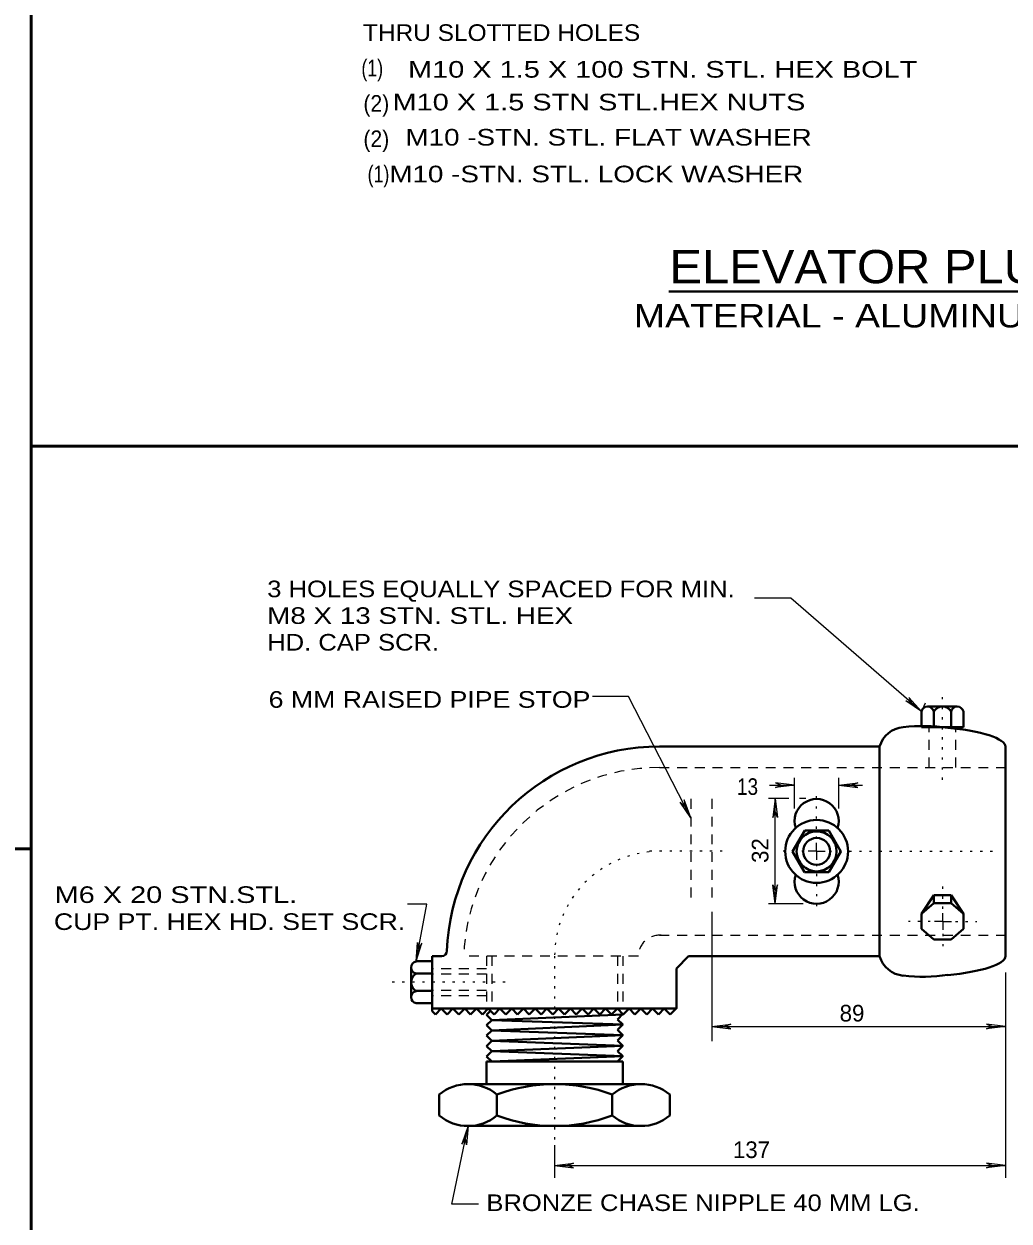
# Model space of a CAD drawing. Extents: x 312583 to 312854, y 144419 to 144597.
# Drawn here: x 312724.6 to 312769.6, y 144481.2 to 144536 of the extents above; entities that cross this region are included whole.
import ezdxf
from ezdxf.enums import TextEntityAlignment as Align

# ---------------------------------------------------------------- set-up
doc = ezdxf.new("R2010")
doc.units = 0
doc.header["$LTSCALE"] = 0.3
doc.linetypes.add('DOTTED', pattern=[1.5, 0.3, -1.2])
doc.linetypes.add('SHORT_DASHED', pattern=[2.7, 1.5, -1.2])
doc.layers.add('1', color=7, linetype='Continuous', lineweight=40)
doc.layers.add('2', color=7, linetype='Continuous', lineweight=13)

msp = doc.modelspace()

# ---------------------------------------------------------------- linework, layer by layer
at = {"layer": '1', "lineweight": 53}
for p, q in [((312805.4109, 144516.6626), (312724.8828, 144516.6626)), ((312724.8828, 144498.2549), (312684.879, 144498.2549))]:
    msp.add_line(p, q, dxfattribs=at)
at = {"layer": '1', "linetype": 'DOTTED', "lineweight": 13}
for p, q in [((312766.533, 144501.4167), (312766.533, 144505.5337)), ((312746.546, 144492.1553), (312741.3404, 144492.1553))]:
    msp.add_line(p, q, dxfattribs=at)
at = {"layer": '1'}
for p, q in [((312767.2, 144504.7593), (312765.843, 144504.7593)), ((312765.5747, 144504.5293), (312765.5747, 144503.8163)), ((312766.1344, 144504.5293), (312766.1344, 144503.8163)), ((312766.9317, 144504.5293), (312766.9317, 144503.8163)), ((312767.4914, 144504.5293), (312767.4914, 144503.8163)), ((312765.5747, 144503.8163), (312767.4914, 144503.8163)), ((312759.679, 144498.1353), (312760.2387, 144499.1013)), ((312760.231, 144497.1847), (312759.679, 144498.1353)), ((312766.1344, 144496.1343), (312765.5747, 144495.291)), ((312766.9317, 144496.1343), (312766.1344, 144496.1343)), ((312766.1344, 144496.1343), (312766.1344, 144495.774)), ((312766.9317, 144496.1343), (312766.9317, 144495.774)), ((312766.1344, 144495.774), (312765.5747, 144495.291)), ((312766.9317, 144495.774), (312766.1344, 144495.774)), ((312765.5747, 144495.291), (312765.5747, 144494.601)), ((312767.4914, 144495.291), (312767.4914, 144494.601)), ((312765.5747, 144494.601), (312766.1344, 144494.1103)), ((312767.4914, 144494.601), (312766.9317, 144494.1103)), ((312766.9317, 144494.1103), (312766.1344, 144494.1103)), ((312743.211, 144493.3513), (312743.648, 144493.3513)), ((312754.3737, 144492.7917), (312754.9334, 144493.3513)), ((312742.2527, 144492.8223), (312742.2527, 144491.4577)), ((312742.4827, 144493.1137), (312743.1957, 144493.1137)), ((312742.4827, 144492.554), (312743.1957, 144492.554)), ((312742.4827, 144491.7567), (312743.1957, 144491.7567)), ((312742.4827, 144491.197), (312743.1957, 144491.197)), ((312743.625, 144490.9517), (312743.3567, 144490.6833)), ((312743.625, 144490.9517), (312743.8934, 144490.6833)), ((312744.1617, 144490.9517), (312743.8934, 144490.6833)), ((312744.1617, 144490.9517), (312744.43, 144490.6833)), ((312744.6984, 144490.9517), (312744.43, 144490.6833)), ((312744.6984, 144490.9517), (312744.9667, 144490.6833)), ((312745.235, 144490.9517), (312744.9667, 144490.6833)), ((312745.235, 144490.9517), (312745.5034, 144490.6833)), ((312745.7717, 144490.9517), (312745.5034, 144490.6833)), ((312745.7717, 144490.9517), (312746.04, 144490.6833)), ((312746.3084, 144490.9517), (312746.04, 144490.6833)), ((312746.3084, 144490.9517), (312746.5767, 144490.6833)), ((312746.845, 144490.9517), (312746.5767, 144490.6833)), ((312746.845, 144490.9517), (312747.1134, 144490.6833)), ((312747.3817, 144490.9517), (312747.1134, 144490.6833)), ((312747.3817, 144490.9517), (312747.65, 144490.6833)), ((312747.9184, 144490.9517), (312747.65, 144490.6833)), ((312747.9184, 144490.9517), (312748.1867, 144490.6833)), ((312748.455, 144490.9517), (312748.1867, 144490.6833)), ((312748.455, 144490.9517), (312748.7234, 144490.6833)), ((312748.9917, 144490.9517), (312748.7234, 144490.6833)), ((312748.9917, 144490.9517), (312749.26, 144490.6833)), ((312749.5284, 144490.9517), (312749.26, 144490.6833)), ((312749.5284, 144490.9517), (312749.7967, 144490.6833)), ((312750.065, 144490.9517), (312749.7967, 144490.6833)), ((312750.065, 144490.9517), (312750.3334, 144490.6833)), ((312750.6017, 144490.9517), (312750.3334, 144490.6833)), ((312750.6017, 144490.9517), (312750.87, 144490.6833)), ((312751.1384, 144490.9517), (312750.87, 144490.6833)), ((312751.1384, 144490.9517), (312751.4067, 144490.6833)), ((312751.675, 144490.9517), (312751.4067, 144490.6833)), ((312751.675, 144490.9517), (312751.9434, 144490.6833)), ((312752.2117, 144490.9517), (312751.9434, 144490.6833)), ((312752.2117, 144490.9517), (312752.48, 144490.6833)), ((312752.7484, 144490.9517), (312752.48, 144490.6833)), ((312752.7484, 144490.9517), (312753.0167, 144490.6833)), ((312753.285, 144490.9517), (312753.0167, 144490.6833)), ((312753.285, 144490.9517), (312753.5534, 144490.6833)), ((312753.8217, 144490.9517), (312753.5534, 144490.6833)), ((312753.8217, 144490.9517), (312754.09, 144490.6833)), ((312754.3737, 144490.9747), (312754.09, 144490.6833)), ((312743.211, 144490.829), (312743.3567, 144490.6833)), ((312745.8714, 144490.852), (312745.695, 144490.668)), ((312745.9327, 144490.4303), (312745.695, 144490.668)), ((312745.9327, 144490.4303), (312745.695, 144490.1927)), ((312751.6827, 144490.461), (312751.9204, 144490.7063)), ((312751.6827, 144490.461), (312751.9204, 144490.2233)), ((312745.9327, 144489.955), (312745.695, 144490.1927)), ((312745.9327, 144489.955), (312745.695, 144489.7173)), ((312751.6827, 144489.978), (312751.9204, 144490.2233)), ((312751.6827, 144489.978), (312751.9204, 144489.7403)), ((312745.9327, 144489.4797), (312745.695, 144489.7173)), ((312745.9327, 144489.4797), (312745.695, 144489.242)), ((312751.6827, 144489.495), (312751.9204, 144489.7403)), ((312751.6827, 144489.495), (312751.9204, 144489.2573)), ((312745.9327, 144489.0043), (312745.695, 144489.242)), ((312745.9327, 144489.0043), (312745.695, 144488.7667)), ((312745.9327, 144488.529), (312745.695, 144488.7667)), ((312751.6827, 144489.012), (312751.9204, 144489.2573)), ((312751.6827, 144489.012), (312751.9204, 144488.7743)), ((312751.6827, 144488.529), (312751.9204, 144488.7743)), ((312745.695, 144488.529), (312745.695, 144487.5017)), ((312745.695, 144488.529), (312751.9204, 144488.529)), ((312751.9204, 144488.529), (312751.9204, 144487.5017)), ((312744.8517, 144487.5017), (312752.7637, 144487.5017)), ((312744.8517, 144485.585), (312752.7637, 144485.585))]:
    msp.add_line(p, q, dxfattribs=at)
at = {"layer": '1', "linetype": 'SHORT_DASHED', "lineweight": 25}
for p, q in [((312765.9197, 144501.9763), (312765.9197, 144503.8163)), ((312767.1464, 144501.9763), (312767.1464, 144503.8163)), ((312752.641, 144493.3513), (312744.6524, 144493.3513)), ((312745.695, 144492.7687), (312743.1957, 144492.7687)), ((312745.695, 144492.531), (312743.1957, 144492.531)), ((312745.695, 144491.7797), (312743.1957, 144491.7797)), ((312745.695, 144491.542), (312743.1957, 144491.542))]:
    msp.add_line(p, q, dxfattribs=at)
at = {"layer": '1', "lineweight": 53}
msp.add_lwpolyline([(312724.8828, 144479.6096), (312724.8828, 144516.6626), (312724.8828, 144585.0846)], dxfattribs=at)
at = {"layer": '1'}
for points in [[(312761.335, 144497.1847), (312761.887, 144498.1353), (312761.335, 144499.1013)], [(312766.9317, 144496.1343), (312767.4914, 144495.291), (312766.9317, 144495.774)], [(312745.9327, 144488.529), (312751.9204, 144488.7743), (312745.9327, 144489.0043), (312751.9204, 144489.2573), (312745.9327, 144489.4797), (312751.9204, 144489.7403), (312745.9327, 144489.955), (312751.9204, 144490.2233), (312745.9327, 144490.4303), (312751.9434, 144490.6833)]]:
    msp.add_lwpolyline(points, dxfattribs=at)
for radius in [1.4375, 0.9135, 0.6133]:
    msp.add_circle((312760.783, 144498.1392), radius, dxfattribs=at)
for centre, radius, start, end in [((312765.8545, 144504.4744), 0.2852, 11.10854, 168.89146), ((312766.533, 144504.2988), 0.4605, 30.03672, 149.96328), ((312767.2115, 144504.4744), 0.2852, 11.10854, 168.89146), ((312764.8567, 144502.5781), 1.2495, 95.48732, 163.60099), ((312765.6264, 144495.9806), 7.8896, 81.60394, 96.45767), ((312760.783, 144499.5265), 1.0085, 341.857, 198.14299), ((312760.783, 144496.7518), 1.0085, 161.85701, 18.143), ((312743.6446, 144493.5909), 0.2396, 270, 358.87648), ((312764.8567, 144493.7003), 1.2495, 196.39901, 264.51268), ((312742.5338, 144492.83), 0.2852, 101.10854, 258.89146), ((312742.7094, 144492.1515), 0.4605, 120.03672, 239.96328), ((312765.6264, 144500.2977), 7.8896, 263.54233, 278.39606), ((312742.5338, 144491.473), 0.2852, 101.10854, 258.89146), ((312744.8517, 144485.4476), 2.0541, 50.06054, 129.93946), ((312748.8058, 144480.0147), 7.487, 69.3903, 110.6097), ((312752.7579, 144485.4529), 2.0488, 50.00694, 129.99307), ((312744.8517, 144487.6391), 2.0541, 230.06054, 309.93946), ((312748.8058, 144493.072), 7.487, 249.3903, 290.6097), ((312752.7579, 144487.6338), 2.0488, 230.00694, 309.99307)]:
    msp.add_arc(centre, radius, start, end, dxfattribs=at)
at = {"layer": '1', "linetype": 'SHORT_DASHED', "lineweight": 25}
for centre, radius, start, end in [((312753.5955, 144493.0217), 8.9516, 90, 177.914), ((312753.5955, 144493.3475), 0.9583, 85.17923, 180)]:
    msp.add_arc(centre, radius, start, end, dxfattribs=at)
at = {"layer": '1', "linetype": 'DOTTED', "lineweight": 13}
msp.add_arc((312753.5955, 144493.3475), 4.7917, 95.60113, 180, dxfattribs=at)
at = {"layer": '1'}
for centre, major_axis, start_param, end_param in [((312766.5417, 144503.1303), (-2.868, 0.2006), 3.1430433, 4.6456527), ((312766.5417, 144493.1481), (-2.868, -0.2006), 1.6375326, 3.140142)]:
    msp.add_ellipse(centre, major_axis=major_axis, ratio=0.235384, start_param=start_param, end_param=end_param, dxfattribs=at)
at = {"layer": '2', "lineweight": 40}
for p, q in [((312754.0223, 144523.7389), (312779.6055, 144523.7389)), ((312753.5994, 144502.9347), (312763.658, 144502.9347)), ((312763.658, 144502.9347), (312763.658, 144493.3513)), ((312769.408, 144502.9347), (312769.408, 144493.3513)), ((312760.2387, 144499.1013), (312761.335, 144499.1013)), ((312760.231, 144497.1847), (312761.335, 144497.1847)), ((312743.211, 144493.3513), (312743.211, 144490.829)), ((312754.9334, 144493.3513), (312763.658, 144493.3513)), ((312754.3737, 144492.7917), (312754.3737, 144490.9517)), ((312743.211, 144490.9517), (312754.3737, 144490.9517)), ((312743.533, 144487.0263), (312743.533, 144486.068)), ((312746.1704, 144487.0263), (312746.1704, 144486.068)), ((312751.445, 144487.0263), (312751.445, 144486.068)), ((312754.0747, 144487.0263), (312754.0747, 144486.068))]:
    msp.add_line(p, q, dxfattribs=at)
at = {"layer": '2'}
for p, q in [((312764.992, 144505.181), (312765.13, 144504.9203)), ((312765.5747, 144504.5293), (312764.992, 144505.181)), ((312764.854, 144505.02), (312765.13, 144504.9203)), ((312765.5747, 144504.5293), (312764.854, 144505.02)), ((312759.771, 144500.1057), (312759.771, 144501.5087)), ((312761.795, 144500.1057), (312761.795, 144501.5087)), ((312758.6287, 144501.1637), (312759.771, 144501.1637)), ((312758.9047, 144501.271), (312759.1807, 144501.1637)), ((312759.771, 144501.1637), (312758.9047, 144501.271)), ((312758.9047, 144501.0563), (312759.1807, 144501.1637)), ((312759.771, 144501.1637), (312758.9047, 144501.0563)), ((312761.795, 144501.1637), (312762.6614, 144501.271)), ((312761.795, 144501.1637), (312762.8837, 144501.1637)), ((312761.795, 144501.1637), (312762.6614, 144501.0563)), ((312762.6614, 144501.271), (312762.3854, 144501.1637)), ((312762.6614, 144501.0563), (312762.3854, 144501.1637)), ((312754.5424, 144500.397), (312754.7647, 144500.1977)), ((312755.033, 144499.6763), (312754.5424, 144500.397)), ((312754.734, 144500.4967), (312754.7647, 144500.1977)), ((312755.033, 144499.6763), (312754.734, 144500.4967)), ((312759.5104, 144500.5503), (312758.5904, 144500.5503)), ((312758.8817, 144500.5503), (312758.7744, 144499.684)), ((312758.8817, 144495.7433), (312758.8817, 144500.5503)), ((312758.8817, 144500.5503), (312758.989, 144499.684)), ((312760.2924, 144500.5503), (312760.001, 144500.5503)), ((312758.7744, 144499.684), (312758.8817, 144499.96)), ((312758.989, 144499.684), (312758.8817, 144499.96)), ((312760.783, 144498.143), (312760.3997, 144498.143)), ((312760.783, 144498.143), (312760.783, 144498.5263)), ((312760.783, 144498.143), (312761.1664, 144498.143)), ((312760.783, 144498.143), (312760.783, 144497.7597)), ((312758.7744, 144496.6097), (312758.8817, 144496.3337)), ((312758.8817, 144495.7433), (312758.7744, 144496.6097)), ((312758.989, 144496.6097), (312758.8817, 144496.3337)), ((312758.8817, 144495.7433), (312758.989, 144496.6097)), ((312755.9914, 144495.383), (312755.9914, 144489.4643)), ((312760.162, 144495.7433), (312758.5904, 144495.7433)), ((312766.5484, 144494.9383), (312766.165, 144494.9383)), ((312766.5484, 144494.9383), (312766.5484, 144495.3217)), ((312766.5484, 144494.9383), (312766.9394, 144494.9383)), ((312766.5484, 144494.9383), (312766.5484, 144494.555)), ((312742.4827, 144493.1137), (312742.5364, 144493.98)), ((312742.4827, 144493.1137), (312742.7434, 144493.9417)), ((312742.5364, 144493.98), (312742.59, 144493.6887)), ((312742.7434, 144493.9417), (312742.59, 144493.6887)), ((312769.408, 144492.6), (312769.408, 144483.2083)), ((312755.9914, 144490.1313), (312756.8577, 144490.2387)), ((312755.9914, 144490.1313), (312769.408, 144490.1313)), ((312755.9914, 144490.1313), (312756.8577, 144490.024)), ((312756.8577, 144490.2387), (312756.5817, 144490.1313)), ((312756.8577, 144490.024), (312756.5817, 144490.1313)), ((312768.5417, 144490.2387), (312768.8177, 144490.1313)), ((312769.408, 144490.1313), (312768.5417, 144490.2387)), ((312768.5417, 144490.024), (312768.8177, 144490.1313)), ((312769.408, 144490.1313), (312768.5417, 144490.024)), ((312744.8517, 144485.585), (312744.568, 144484.757)), ((312744.8517, 144485.585), (312744.7827, 144484.7187)), ((312744.568, 144484.757), (312744.7367, 144485.01)), ((312744.7827, 144484.7187), (312744.7367, 144485.01)), ((312748.8077, 144484.711), (312748.8077, 144483.2083)), ((312748.8077, 144483.7833), (312749.674, 144483.8907)), ((312749.674, 144483.8907), (312749.398, 144483.7833)), ((312768.5417, 144483.8907), (312768.8177, 144483.7833)), ((312769.408, 144483.7833), (312768.5417, 144483.8907)), ((312748.8077, 144483.7833), (312769.408, 144483.7833)), ((312748.8077, 144483.7833), (312749.674, 144483.676)), ((312749.674, 144483.676), (312749.398, 144483.7833)), ((312768.5417, 144483.676), (312768.8177, 144483.7833)), ((312769.408, 144483.7833), (312768.5417, 144483.676))]:
    msp.add_line(p, q, dxfattribs=at)
at = {"layer": '2', "linetype": 'SHORT_DASHED', "lineweight": 25}
for p, q in [((312753.5994, 144501.9763), (312769.408, 144501.9763)), ((312755.033, 144500.535), (312755.033, 144495.7433)), ((312755.9914, 144500.535), (312755.9914, 144495.7433)), ((312753.5994, 144494.3097), (312769.408, 144494.3097)), ((312745.695, 144493.3513), (312745.695, 144490.9517)), ((312745.9327, 144493.3513), (312745.9327, 144490.9517)), ((312751.6827, 144493.3513), (312751.6827, 144490.9517)), ((312751.9204, 144493.3513), (312751.9204, 144490.9517))]:
    msp.add_line(p, q, dxfattribs=at)
at = {"layer": '2', "linetype": 'DOTTED'}
for p, q in [((312760.783, 144498.718), (312760.783, 144500.8723)), ((312756.4667, 144498.143), (312753.1317, 144498.143)), ((312760.208, 144498.143), (312759.2497, 144498.143)), ((312761.358, 144498.143), (312768.925, 144498.143)), ((312760.783, 144497.568), (312760.783, 144495.3293)), ((312766.5484, 144495.5133), (312766.5484, 144496.7093)), ((312765.9734, 144494.9383), (312764.9844, 144494.9383)), ((312767.131, 144494.9383), (312768.1124, 144494.9383)), ((312766.5484, 144494.3633), (312766.5484, 144493.5813)), ((312748.8077, 144493.3513), (312748.8077, 144484.711))]:
    msp.add_line(p, q, dxfattribs=at)
at = {"layer": '2'}
for points in [[(312765.7434, 144504.9203), (312765.5747, 144504.5293), (312759.6024, 144509.712), (312757.9464, 144509.712)], [(312755.033, 144499.6763), (312752.1887, 144505.2193), (312750.5327, 144505.2193)], [(312742.4827, 144493.1137), (312742.9657, 144495.7203), (312742.0764, 144495.7203)], [(312745.327, 144482.0047), (312744.108, 144482.0047), (312744.8517, 144485.585)]]:
    msp.add_lwpolyline(points, dxfattribs=at)
at = {"layer": '2', "lineweight": 40}
msp.add_arc((312753.5955, 144493.2133), 9.7189, 90, 177.80004, dxfattribs=at)

# ---------------------------------------------------------------- texts
at = {"layer": '2'}
for s, width, p in [('THRU SLOTTED HOLES', 1.1, (312740.0467, 144535.1919)), ('(1)', 0.8, (312739.9758, 144533.5742)), ('M10 X 1.5 X 100 STN. STL. HEX BOLT', 1.3, (312742.109, 144533.5129)), ('(2)', 0.95, (312740.0676, 144531.9566)), ('  M10 X 1.5 STN STL.HEX NUTS', 1.3, (312740.6635, 144532.0179)), ('(2)', 0.95, (312740.0676, 144530.3389)), (' M10 -STN. STL. FLAT WASHER', 1.25, (312741.639, 144530.4079)), ('(1)', 0.8, (312740.2593, 144528.7289)), ('   M10 -STN. STL. LOCK WASHER', 1.25, (312740.1936, 144528.7289)), ('3 HOLES EQUALLY SPACED FOR MIN.', 1.15, (312735.6704, 144509.7589)), ('M8 X 13 STN. STL. HEX', 1.25, (312735.6704, 144508.5389)), ('HD. CAP SCR.', 1.15, (312735.6704, 144507.3189)), ('6 MM RAISED PIPE STOP', 1.2, (312735.7365, 144504.7047)), ('13', 0.85, (312757.145, 144500.7209)), ('M6 X 20 STN.STL.', 1.3, (312725.9538, 144495.7817)), ('CUP PT. HEX HD. SET SCR.', 1.2, (312725.921, 144494.5473)), ('BRONZE CHASE NIPPLE 40 MM LG.', 1.15, (312745.6874, 144481.697))]:
    msp.add_text(s, height=0.76, dxfattribs=dict(at, width=width)).set_placement(p)
for s, height, width, p in [('ELEVATOR PLUMBIZER', 1.52, 1.1, (312766.7227, 144524.1146)), ('MATERIAL - ALUMINUM ALLOY 356', 1.07, 1.2, (312766.7372, 144522.094))]:
    msp.add_text(s, height=height, dxfattribs=dict(at, width=width)).set_placement(p, align=Align.CENTER)
msp.add_text('32', height=0.76, rotation=90, dxfattribs=at).set_placement((312758.5793, 144497.6129))
for s, p in [('89', (312761.8355, 144490.3632)), ('137', (312756.9575, 144484.1216))]:
    msp.add_text(s, height=0.76, dxfattribs=at).set_placement(p)

doc.saveas('drawing.dxf')
